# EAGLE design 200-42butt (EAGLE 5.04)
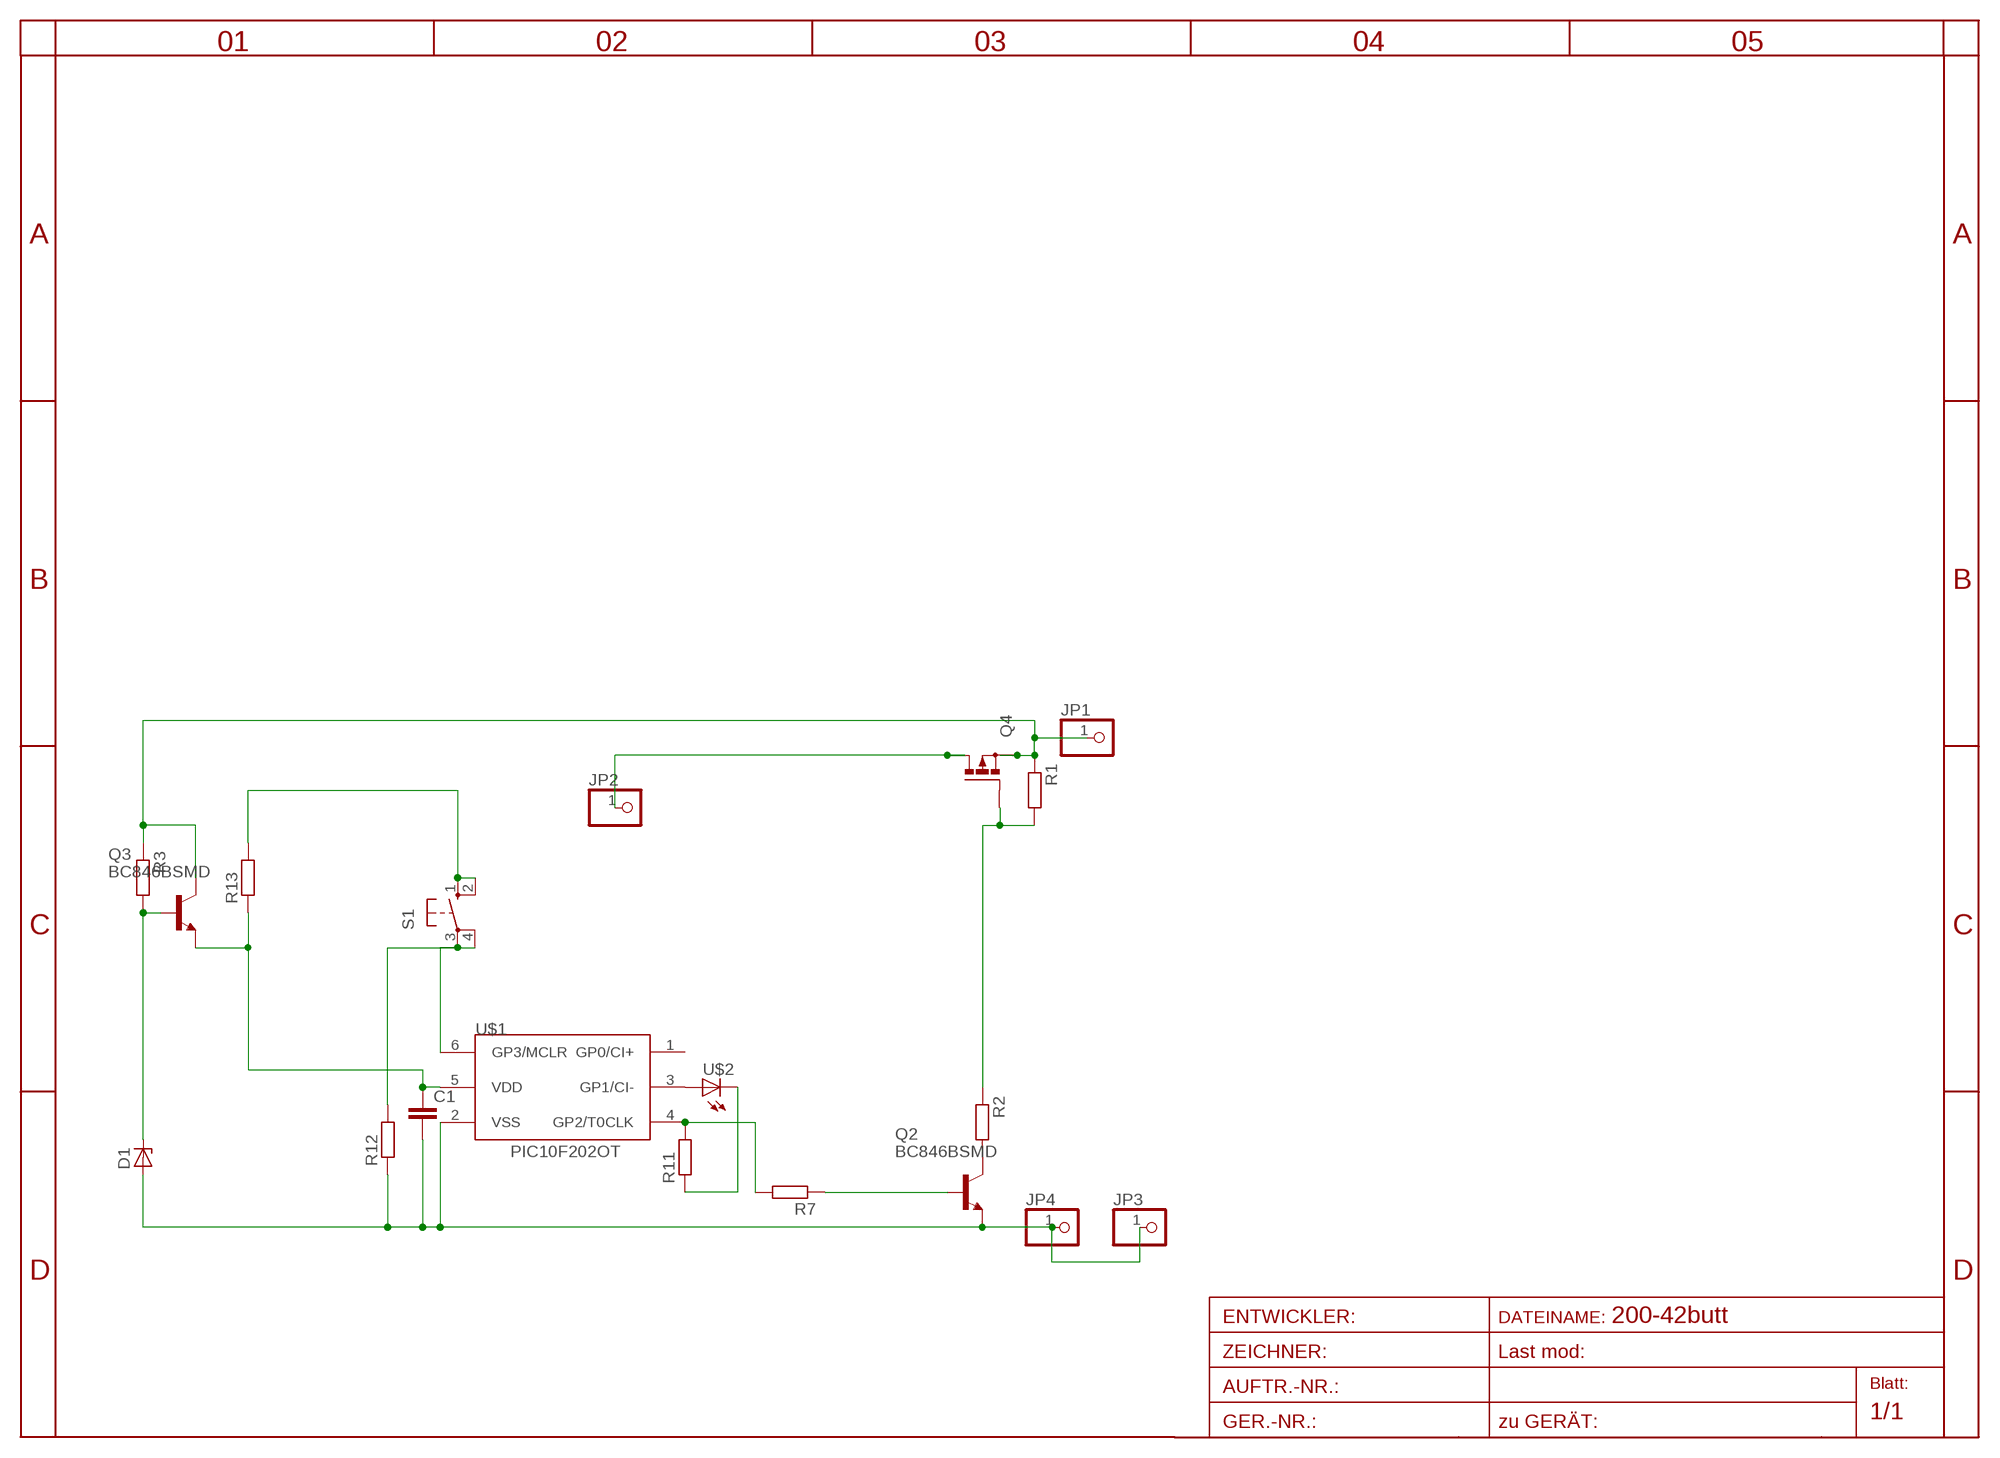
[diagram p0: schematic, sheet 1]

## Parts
C1  C-EUC1206  [C1206]
D1  ZENER-DIODESOD80C  [SOD80C]
JP1  PINHD-1X1  [1X01]
JP2  PINHD-1X1  [1X01]
JP3  PINHD-1X1  [1X01]
JP4  PINHD-1X1  [1X01]
Q2  BC846BSMD  [SOT23]
Q3  BC846BSMD  [SOT23]
Q4  PMOSFET_PTO220BV  [TO220BV]
R1  R-EU_R0805  [R0805]
R2  R-EU_R0805  [R0805]
R3  R-EU_R0805  [R0805]
R7  R-EU_R1206  [R1206]
R11  R-EU_R0805  [R0805]
R12  R-EU_R0805  [R0805]
R13  R-EU_R0805  [R0805]
S1  10-XX  [B3F-10XX]
U$1  PIC10F202OT  [SOT23-6]
U$2  LED3MM  [LED3MM]

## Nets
GND: C1.2 D1.A JP3.1 JP4.1 Q2.2(E) R12.1 U$1.2(VSS)
GP2: R7.2 R11.2 U$1.4(GP2/T0CLK)
GP3: R12.2 S1.3(P) S1.4(P1) U$1.6(GP3/MCLR)
N$3: Q2.3(C) R2.2
N$4: D1.C Q3.1(B) R3.2
N$5: U$1.3(GP1/CI-) U$2.A
N$6: R11.1 U$2.K(C)
N$7: Q4.G R1.2 R2.1
N$10: Q2.1(B) R7.1
N$15: R13.2 S1.1(S) S1.2(S1)
V+IN: JP1.1 Q3.3(C) Q4.S R1.1 R3.1
V+OUT: JP2.1 Q4.D
VDD: C1.1 Q3.2(E) R13.1 U$1.5(VDD)
Unconnected: U$1.1(GP0/CI+)

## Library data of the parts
C1 = rcl:C-EU: CAPACITOR, European symbol
D1 = diode-1:ZENER-DIODE: Z-Diode
JP1-JP4 = pinhead:PINHD-1X1: PIN HEADER
Q2 Q3 = transistor-npn:BC846*: NPN Transistor
Q4 = transistor-power:PMOSFET_P: Power MOSFET P-Channel
R1-R3 R7 R11-R13 = rcl:R-EU_: RESISTOR, European symbol
S1 = switch-omron:10-XX: OMRON SWITCH
U$1 = microchip-5:PIC10F2*: uPC nW 0,25/0,5k Program Flash memory Comparator
U$2 = led(2):LED: LED

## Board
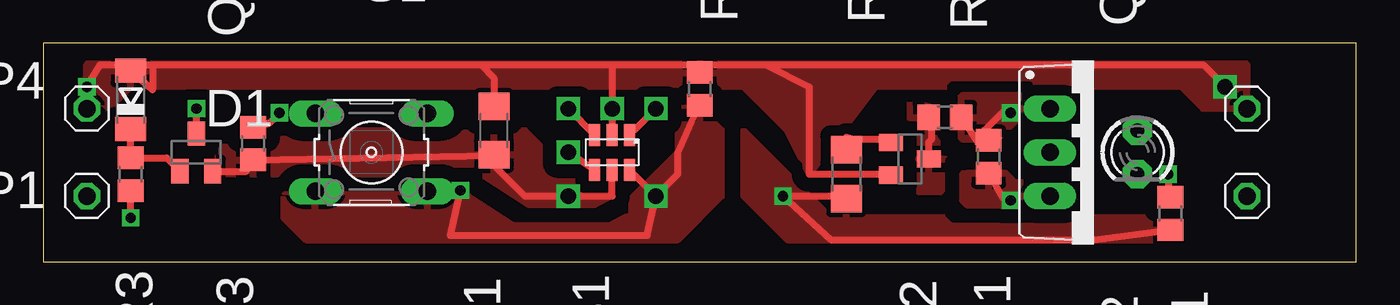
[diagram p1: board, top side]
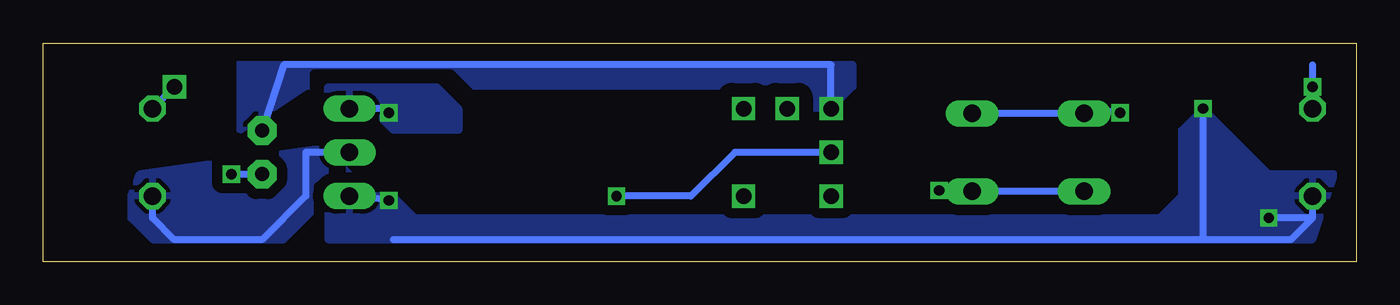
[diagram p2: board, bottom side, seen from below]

Size 76.2 x 12.7 mm. Coordinates in mm from the lower left corner, seen from the top.
Outline: 0,0 76.2,0 76.2,12.7 0,12.69 0,0
Copper layers (1*16): Top 0.035mm / dielectric 1.5mm / Bottom 0.035mm
Design rules "default": minimum track width 10mil, minimum drill 24mil, track to track 8mil, track to pad 8mil, pad to pad 8mil, via to via 8mil, smd to smd 8mil, copper to edge 40mil, drill to drill 8mil, minimum pad ring 10mil, minimum via ring 8mil, stop-mask expansion 4mil, vias tented up to drill 0mil, thermal gap 10mil

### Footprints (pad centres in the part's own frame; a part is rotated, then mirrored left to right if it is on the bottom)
C1206 = smd 1.6 x 1.8: 1 -1.4,0; 2 1.4,0
SOD80C = smd 1.4 x 1.8: A 1.7,0; C -1.7,0
1X01 = drill 1.016 octagon: 1 0,0
SOT23 = smd 1 x 1.4: 1 -0.95,-1.1; 2 0.95,-1.1; 3 0,1.1
TO220BV = drill 1.016 long: D 0,-2.54; G -2.54,-2.54; S 2.54,-2.54
R0805 = smd 1.3 x 1.5: 1 -0.95,0; 2 0.95,0
R1206 = smd 1.6 x 1.803: 1 -1.422,0; 2 1.422,0
B3F-10XX = drill 1.016 long: 1 -3.251,2.261; 2 3.251,2.261; 3 -3.251,-2.261; 4 3.251,-2.261
SOT23-6 = smd 0.635 x 1.27: 1 -1.016,-1.016; 2 0,-1.016; 3 1.016,-1.016; 4 1.016,1.016; 5 0,1.016; 6 -1.016,1.016
LED3MM = drill 0.813 pad 1.676 octagon: A -1.27,0; K 1.27,0

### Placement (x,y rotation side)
C1  26.16,7.62 90 top
D1  5.08,9.4 90 top
JP1  2.54,3.81 0 top
JP2  69.85,3.81 0 top
JP3  69.85,8.89 0 top
JP4  2.54,8.89 0 top
Q2  50.29,5.97 270 top
Q3  8.89,6.35 0 top
Q4  60.96,6.35 270 top
R1  54.86,6.1 90 top
R2  52.32,8.38 180 top
R3  5.08,5.08 90 top
R7  46.61,5.08 270 top
R11  65.41,2.79 270 top
R12  38.1,10.03 270 top
R13  12.19,6.86 90 top
S1  19.05,6.35 0 top
U$1  33.02,6.35 180 top
U$2  63.5,6.35 270 top

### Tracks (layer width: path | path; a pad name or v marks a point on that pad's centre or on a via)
GND  (via drill 0.6, 0.9 pad 1.27)
  Top 0.406: U$1.2 v33.02,8.89 33.02,11.43 | D1.A 6.35,9.99 6.35,11.43 | 6.35,11.43 3.3,11.43 v2.54,10.16 | C1.2 26.16,10.67 25.4,11.43 | 6.35,11.43 25.4,11.43 | 25.4,11.43 33.02,11.43 | Q2.2 48.45,5.08 44.45,5.08 44.45,10.16 41.91,11.43 | 33.02,11.43 38.1,11.43 | 38.1,11.43 41.91,11.43 | v68.58,10.16 67.31,11.43 41.91,11.43 | 38.1,11.43 R12.1
  Bottom 0.406: 2.54,11.43 JP4.1 v2.54,10.16 | v68.58,10.16 JP3.1
  pour Top (isolate 0.61, rank 3): 2.54,10.16 2.54,11.43 3.81,12.7 68.58,12.7 69.85,11.43 69.85,8.89 67.31,8.89 66.04,10.16 48.26,10.16 44.45,5.08 43.18,7.62 40.64,10.16 5.08,10.16 3.81,8.89
GP2  (via drill 0.6, 0.9 pad 1.27)
  Top 0.406: R11.2 60.96,1.27 45.72,1.27 v42.93,3.81 46,3.81 R7.2 | U$1.4 v30.48,6.35
  Bottom 0.406: v42.93,3.81 38.61,3.81 36.07,6.35 v30.48,6.35 30.48,6.1
  pour Top (isolate 0.813, rank 2): 40.64,7.62 40.64,3.81 43.18,1.27 64.77,1.27 64.77,2.54 45.72,2.54 44.45,3.81
GP3  (via drill 0.6, 0.9 pad 1.27)
  Top 0.406: v35.56,3.81 35.56,4.26 35.11,4.26 U$1.6 | v24.21,4.14 23.62,1.52 35.05,1.52 v35.56,3.81 | R12.2 37.85,8.64 36.83,6.35 36.83,5.08 v35.56,3.81
  Bottom 0.406: v24.21,4.14 S1.4 S1.3
  pour Top (isolate 0.813, rank 2): 13.97,3.81 13.97,2.54 15.24,1.27 36.83,1.27 39.37,3.81 39.37,7.62 38.1,8.89 36.83,8.89 36.83,6.35 33.02,2.54 27.94,2.54 25.4,5.08 15.24,5.08
N$1  (via drill 0.9 pad 1.27)
  Top 0.406: 34.29,7.62 v35.56,8.89
N$3
  Top 0.406: Q2.3 51.39,6.94 51.56,7.11 51.56,8.06 R2.2
  pour Top (isolate 0.813, rank 2): 52.07,8.89 51.82,8.89 50.8,9.14 50.29,9.14 50.29,4.57 50.8,4.06 52.07,4.06 52.58,4.57
N$4
  Top 0.406: D1.C R3.2 7.16,6.03 Q3.1
N$5  (via drill 0.9 pad 1.27)
  Top 0.406: U$1.3 v30.48,8.89
  Bottom 0.406: U$2.A 62.23,11.43 30.48,11.43 v30.48,8.89
  pour Bottom (isolate 0.813, rank 3): 64.77,7.62 64.77,12.7 30.48,12.7 29.21,11.43 29.21,10.16 30.48,8.89 31.75,8.89 31.75,10.16 60.96,10.16
N$6  (via drill 0.6)
  Top 0.406: v65.28,5.08 65.34,4.06 R11.1
  Bottom 0.406: v65.28,5.08 U$2.K
N$7  (via drill 0.6)
  Top 0.406: R2.1 54.29,6.82 R1.2 54.61,7.62 55.88,8.89 v56.13,8.64
  Bottom 0.406: Q4.G 56.39,8.89 v56.13,8.64
  pour Top (isolate 0.813): 57.15,8.89 57.15,9.14 56.64,9.65 53.34,9.65 53.09,9.4 53.09,7.37 53.34,7.11 55.37,7.11
  pour Bottom (isolate 0.813, rank 2): 59.69,8.89 59.69,10.16 53.34,10.16 52.07,8.89 52.07,7.62 55.88,7.62 57.15,8.89
N$10
  Top 0.406: R7.1 46.61,7.24 46.99,7.11 48.49,7.11 Q2.1
N$15  (via drill 0.6)
  Top 0.406: R13.2 13.14,8.06 v13.72,8.64
  Bottom 0.406: v13.72,8.64 15.52,8.89 S1.1 S1.2
V+IN  (via drill 0.6)
  Top 0.406: v8.89,8.89 Q3.3 | v5.08,2.54 R3.1 | R1.1 55.73,3.66 v56.13,3.56
  Bottom 0.406: 2.54,2.54 3.81,1.27 8.89,1.27 | 8.89,1.27 55.88,1.27 | 8.89,1.27 v8.89,8.89 | 2.54,2.54 v5.08,2.54 | 2.54,2.54 JP1.1 | v56.13,3.56 57.91,3.81
  pour Bottom (isolate 0.61): 1.27,5.08 5.08,5.08 8.89,8.89 10.16,7.62 10.16,3.81 11.43,2.54 54.61,2.54 55.88,3.81 59.69,3.81 59.69,1.27 2.54,1.27
  pour Top (isolate 0.813): 53.34,5.08 53.34,3.81 53.34,3.56 53.59,3.3 57.4,3.3 57.66,3.56 57.66,3.81 56.9,4.57 56.39,4.57 55.63,5.33
V+OUT
  Bottom 0.406: JP2.1 69.85,2.54 68.58,1.27 63.5,1.27 60.96,3.81 60.96,6.35 Q4.D
  pour Bottom (isolate 0.61, rank 2): 59.94,6.6 70.61,5.08 71.12,3.81 71.12,2.54 69.85,1.27 62.23,1.27 58.42,5.08
VDD  (via drill 0.9 pad 1.27)
  Top 0.406: Q3.2 11.79,5.25 R13.1 26.1,6.16 C1.1 26.16,5.59 27.94,3.81 v30.48,3.81 33.02,3.81 U$1.5
  pour Top (isolate 0.813): 10.16,6.35 11.43,7.62 27.94,7.62 30.48,5.08 31.75,5.08 33.02,3.81 32,3.3 28.19,3.3 25.4,5.08 10.16,5.08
